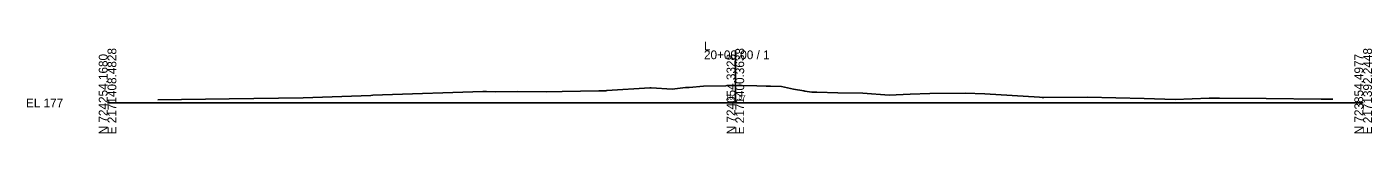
# Model space of a CAD drawing. Extents: x -26 to 2803, y -10 to 9553.
# Drawn here: x 974.3 to 1402.8, y 5990.3 to 6019.5 of the extents above; entities that cross this region are included whole.
import ezdxf

# ---------------------------------------------------------------- set-up
doc = ezdxf.new("R2010")
doc.units = 0
for name, color, linetype in [('Exist Cross Section Cell', 7, 'Continuous'), ('Exist XS Center Line Elevation Label', 7, 'Continuous'), ('Exist XS Ground Line', 7, 'Continuous')]:
    doc.layers.add(name, color=color, linetype=linetype)

msp = doc.modelspace()

# ---------------------------------------------------------------- linework, layer by layer
at = {"layer": 'Exist Cross Section Cell'}
for p, q in [((1200, 6000), (1200, 6016.73)), ((1000, 6000), (1200, 6000)), ((1200, 6000), (1400, 6000))]:
    msp.add_line(p, q, dxfattribs=at)
at = {"layer": 'Exist XS Ground Line'}
msp.add_lwpolyline([(1015.98, 6000.94), (1038.73, 6001.28), (1062.34, 6001.58), (1083.84, 6002.33), (1084.47, 6002.45), (1087.59, 6002.63), (1119.59, 6003.66), (1120.73, 6003.62), (1123.52, 6003.49), (1130.67, 6003.64), (1139.78, 6003.49), (1144.87, 6003.65), (1156.48, 6003.87), (1158.75, 6003.89), (1159.1, 6003.94), (1172.77, 6004.78), (1173.13, 6004.8), (1179.89, 6004.39), (1183.23, 6004.77), (1184.13, 6004.91), (1185.28, 6004.97), (1189.82, 6005.32), (1196.93, 6005.5), (1199.94, 6005.58), (1206.89, 6005.43), (1209.82, 6005.36), (1211.18, 6005.32), (1214.74, 6005.23), (1218.55, 6004.4), (1221.83, 6003.81), (1222.14, 6003.75), (1224.39, 6003.39), (1225.9, 6003.4), (1232.59, 6003.23), (1240.62, 6003.14), (1248.99, 6002.52), (1255.67, 6002.77), (1261.92, 6002.97), (1273.23, 6003.08), (1279.43, 6002.87), (1296.87, 6001.79), (1297.73, 6001.73), (1298.29, 6001.73), (1312.21, 6001.82), (1330.2, 6001.4), (1340.11, 6001.06), (1350.89, 6001.48), (1352.34, 6001.51), (1354.28, 6001.51), (1369.08, 6001.42), (1386.59, 6001.22), (1389.05, 6001.16), (1389.75, 6001.17), (1390.3, 6001.16)], dxfattribs=at)

# ---------------------------------------------------------------- texts
at = {"layer": 'Exist Cross Section Cell'}
for s, p in [('E 2171408.4828', (1002.8, 5990)), ('E 2171400.3638', (1202.8, 5990)), ('E 2171392.2448', (1402.8, 5990)), ('N 724254.1680', (1000, 5990)), ('N 724054.3328', (1200, 5990)), ('N 723854.4977', (1400, 5990))]:
    msp.add_text(s, height=2.8, rotation=90, dxfattribs=at).set_placement(p)
for s, p in [('20+00.00 / 1', (1190, 6013.93)), ('L', (1190, 6016.73)), ('EL 177', (974, 5998.6))]:
    msp.add_text(s, height=2.8, dxfattribs=at).set_placement(p)
at = {"layer": 'Exist XS Center Line Elevation Label'}
msp.add_text('182.57', height=1.5, dxfattribs=at).set_placement((1196.95, 6001.07))

doc.saveas('drawing.dxf')
